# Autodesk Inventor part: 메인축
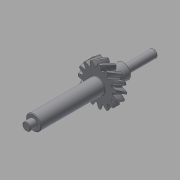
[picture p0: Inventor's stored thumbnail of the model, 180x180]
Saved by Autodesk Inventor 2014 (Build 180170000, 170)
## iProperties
Created: 2016-12
Part Number: 메인축
Material: 강철, 탄소
Document SubType Name: Modeling
Designer: mduedu
Categories: <?xml version="1.0" encoding="UTF-16"?> <MemberInstance><Categories><FamilyTemplate><FamilyTemplateParameter ValueType="xs:double" Id="1" ObjectReferenceKey="da
Density: 7.87 g/cm^3
Appearance: Default
Mass: 199.401 g
Surface Area: 86.9137 cm^2
Volume: 25.3368 cm^3
CustomPartVersion: 1
Author: mduedu
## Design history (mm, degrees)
sketch "Sketch1"
  geometry: C1 r 19.321 at (0, 0)
  constraints: 1 centre point
  dimensions: "d0" = 38.64102 diameter of C1 (= da_da)
extrude "Extrusion1" new body sketch "Sketch1" distance "d1" = 10 (= da_b); taper "d2" = 0 deg
workplane "Work Plane2"
sketch "Sketch2"
  geometry: C1 r 19.321 at (0, 0) reference; C2 r 17.321 at (0, 0)
  constraints: 1 centre point, 1 coincident
  dimensions: "d3" = 34.64102 diameter of C2 (= da_dw)
feature "피치 지름" sketch "Sketch2" dims "d4" = 10, "d5" = 0
workplane "Work Plane8"
workplane "Work Plane9"
feature "스퍼 기어" dims "da_b" = 10, "da_d" = 34.64102, "da_aw" = 43.87862, "da_da" = 38.64102, "da_df" = 29.64102, "da_dw" = 34.64102, angle "da_beta" = 30 deg, "da_lefttooth" = 0, "da_righttooth" = 10
sketch "스케치3"
  geometry: C1 r 7.5 at (0, 0); 1 further point
  constraints: 1 centre point, 1 coincident
  dimensions: "d49" = 15 diameter of C1
extrude "돌출2" join sketch "스케치3" distance "d50" = 64; taper "d51" = 0 deg
sketch "스케치4"
  geometry: C1 r 4 at (0, 0); 1 further point
  constraints: 1 centre point, 1 coincident
  dimensions: "d52" = 8 diameter of C1
extrude "돌출3" join sketch "스케치4" distance "d53" = 7; taper "d54" = 0 deg
sketch "스케치5"
  geometry: C1 r 7.5 at (0, 0) reference; 1 further point
extrude "돌출4" join sketch "스케치5" distance "d55" = 16; taper "d56" = 0 deg
sketch "스케치6"
  geometry: C1 r 4 at (0, 0); 1 further point
  constraints: 1 centre point, 1 coincident
  dimensions: "d57" = 8 diameter of C1
extrude "돌출5" join sketch "스케치6" distance "d58" = 30; taper "d59" = 0 deg
chamfer "모따기1" distance "d60" = 0.5; stored, may be unused: second distance "d61" = 2, angle "d62" = 45 deg
fillet "모깎기1" dims "d63" = 0.5
body "Solid1"
body "Srf1"
other parameters: "d16" = 43.87862 (= da_aw), "d17" = 0, "d34" = 12 deg (computed from da_z), "d39" = 0, "d41" = 0, "d43" = 43.87862 (= da_aw), "d46" = 43.87862 (= da_aw), "d47" = 0, "d48" = 0
